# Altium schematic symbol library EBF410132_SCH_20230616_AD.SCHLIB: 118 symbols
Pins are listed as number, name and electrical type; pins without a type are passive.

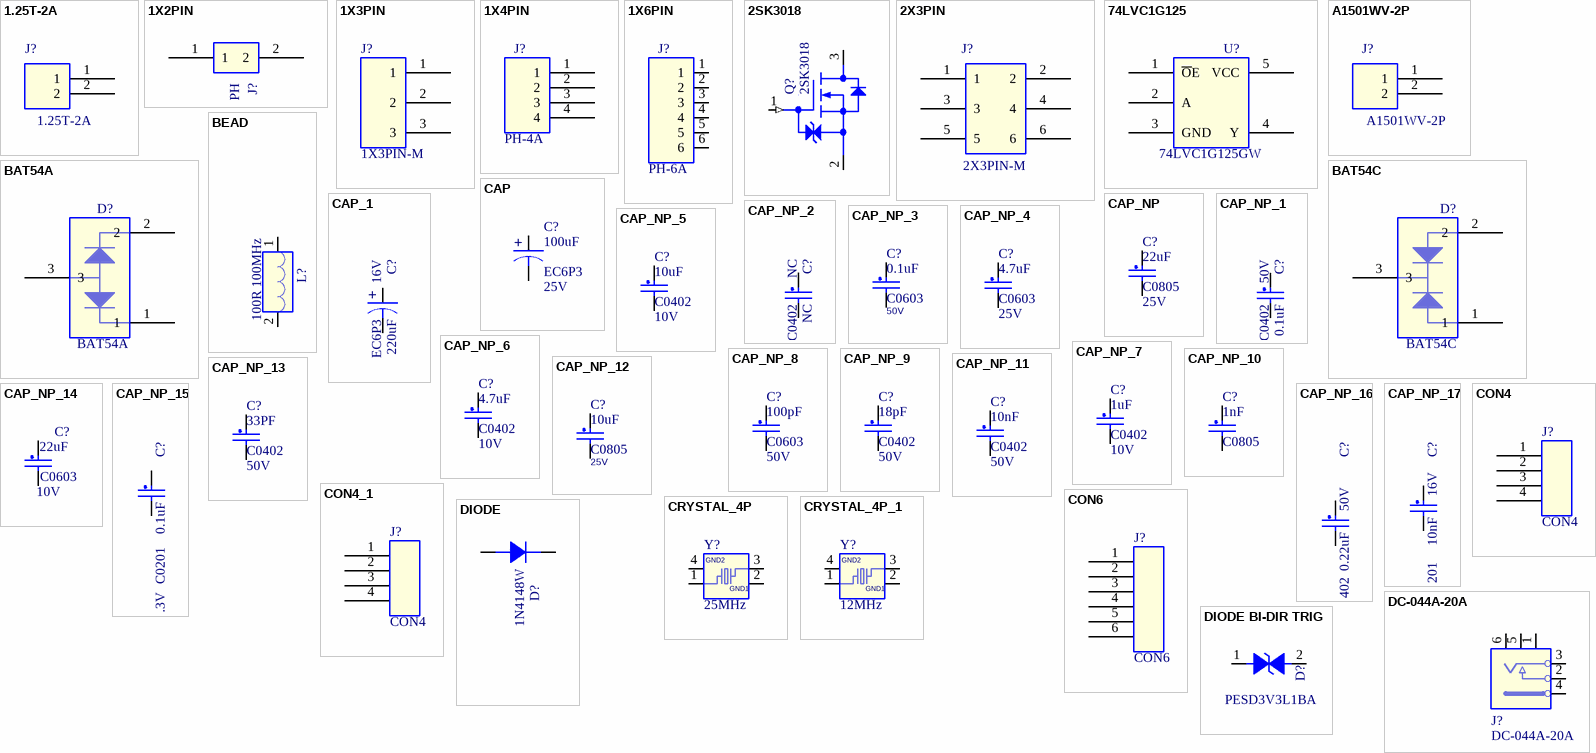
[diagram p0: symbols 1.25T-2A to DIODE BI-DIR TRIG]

## 1.25T-2A
designator J?
生命周期: 量产; 规格书: 1.25T-2A.pdf; 类别: 线对板连接器; 品牌: 创都; 条码: EBF29040105; 规格: GH1.25直插 2P针座连接器; PCB Footprint: gh1p25_th_2p
footprint gh1p25_th_2p
pins: 1, 2

## 1X2PIN
designator J?, comment PH
PCB Footprint: PH-1x2-2P0_l; 规格: 直针PH2.0-2P 间距2.0MM 拔插式 接插件; 规格编号: PH-2A; 条码: EBF29040005; 品牌: 博穆精密; 类别: PH连接器; 规格书: 博穆精密_PH2.0-A.pdf; 价格: 0.019031; 生命周期: 量产
footprint PH-1x2-2P0_l
pins: 1, 2

## 1X3PIN
designator J?, comment 1X3PIN-M
PCB Footprint: DIP_3p_2p54; 规格: 排针 总PIN数3 间距2.54mm 直插; 条码: EBF29020039; 类别: 直插单排排针; 生命周期: 量产; 规格书: 州日_单排针_直插_2P54.pdf
footprint DIP_3p_2p54
pins: 1, 2, 3

## 1X4PIN
designator J?, comment PH-4A
规格: 直针PH2.0-4P 间距2.0MM 拔插式 接插件; 条码: EBF29020025; 品牌: 博穆精密; 类别: PH连接器; 规格书: 博穆精密-PH2.0.pdf; 价格: 0.017; 生命周期: 量产; PCB Footprint: PH-1X4-2P0
footprint PH-1X4-2P0
pins: 1, 2, 3, 4

## 1X6PIN
designator J?, comment PH-6A
PCB Footprint: PH-1X6-2P0; 可替代料: EBF29020026; 生命周期: 量产; 价格: 0.0228; 规格书: 博穆精密_PH2.0-A.pdf; 类别: PH连接器; 品牌: 博穆精密; 规格: 直针PH2.0-6P 间距2.0MM 拔插式 接插件
footprint PH-1X6-2P0
pins: 1, 2, 3, 4, 5, 6

## 2SK3018
designator Q?
CLASS: IC; 丝印: KN; 生命周期: 量产; 价格: 0.120725; 规格书: 长电科技-2SK3018.pdf; 类别: N-MOS; 品牌: 江苏长电; 条码: EBF29280009; 规格: N沟道MOS 导通电阻8Ω 电流10mA 0.8V可驱动; PCB Footprint: SOT23
footprint SOT23
pins: 1 GATE (in), 2 SOURCE, 3 DRAIN

## 2X3PIN
designator J?, comment 2X3PIN-M
PCB Footprint: DIP-2X3-2P54; 生命周期: 量产; 类别: 直插双排排针; 条码: EBF29020030; 规格: 排针 总PIN数6 间距2.54mm 直插; 规格书: 州日_双排针_直插_2P54.pdf
footprint DIP-2X3-2P54
pins: 1, 2, 3, 4, 5, 6

## 74LVC1G125
designator U?, comment 74LVC1G125GW
规格: 时钟缓冲器 驱动器 具有三态输出 允许工作电压为3.3V 5.5V 典型工作电流100mA; 条码: EBF29170001; 品牌: 安世; 类别: 隔离器件; 规格书: 74LVC1G125GW.pdf; 价格: 0.182409; 生命周期: 量产; 丝印: VM; PCB Footprint: SOT-353
footprint SOT-353
pins: 1 ~{O}E, 2 A, 3 GND, 4 Y, 5 VCC

## A1501WV-2P
designator J?
PCB Footprint: zh1p5mm_th_2p; 品牌: 长江连接器; 规格: ZH1.5直插 镀锡 2P 针座连接器; 条码: EBF29040095; 类别: 线对板连接器; 规格书: A1501.pdf; 生命周期: 量产
footprint zh1p5mm_th_2p
pins: 1, 2

## BAT54A
designator D?
规格: 肖特基二极管 直流反向耐压30V 平均整流电流200mA 正向压降1V@100mA SOT-23; 条码: EBF29140065; 品牌: 晶导微电子; 类别: 贴片肖特基二极管; 规格书: 晶导微电子-BAT54S.pdf; 价格: 0.054466; 生命周期: 量产; PCB Footprint: SOT23
footprint SOT23
pins: 1, 2, 3

## BAT54C
designator D?
规格: 肖特基二极管 直流反向耐压30V 平均整流电流200mA 正向压降1V@100mA SOT-23; 条码: EBF29140014; 品牌: 萨科微; 类别: 贴片肖特基二极管; 规格书: BAT54C.pdf; 价格: 0.068489; 生命周期: 量产; 丝印: KL3; PCB Footprint: SOT23
footprint SOT23
pins: 1, 2, 3

## BEAD
designator L?, comment 100R 100MHz
CLASS: DISCRETE; 规格: 磁珠100Ω @100MHz 额定电流3A 直流电阻30mΩ; 规格编号: UPZ1608E101-3R0TF; 条码: EBF29050038; 品牌: 顺络; 类别: 贴片磁珠0603; 规格书: 顺络-磁珠.pdf; 价格: 0.021567; 生命周期: 量产; PCB Footprint: L0603
footprint L0603
pins: 1, 2

## CAP
designator C?, comment 100uF  PCB Footprint: EC6P3  Voltage: 25V
生命周期: 量产; 价格: 0.527539; 规格书: 台湾立隆-贴片型铝电解电容.pdf; 类别: 贴片型铝电解电容; 品牌: 台湾立隆; 条码: EBF29060142; 规格编号: VZL101M1ETR-0606; 规格: 贴片电解电容100uF 20% 25V 尺寸6.3mmX5.7mm 工作寿命：2000H@105℃
footprint T2012
footprint EC6P3
pins: 1, 2

## CAP_1
designator C?, comment 220uF  PCB Footprint: EC6P3  Voltage: 16V
规格: 贴片电解电容220uF 20% 16V 尺寸6.3mmX5.8mm 工作寿命：2000H@105℃; 规格编号: VZT221M1CTR-0606ACS; 条码: EBF29060148; 品牌: 台湾立隆; 类别: 贴片型铝电解电容; 规格书: 台湾立隆-贴片型铝电解电容.pdf; 价格: 0.566564; 生命周期: 量产
footprint T2012
footprint EC6P3
pins: 1, 2

## CAP_NP
designator C?, comment 22uF  PCB Footprint: C0805  Voltage: 25V
CLASS: DISCRETE; 规格: 贴片电容22uF 20% 25V X5R 0805; 规格编号: 0805X226M250NT; 条码: EBF29060173; 品牌: 风华; 类别: 贴片电容0805; 规格书: 风华电容.pdf; 价格: 0.285631; 生命周期: 量产
footprint C0805
pins: 1, 2

## CAP_NP_1
designator C?, comment 0.1uF  PCB Footprint: C0402  Voltage: 50V
CLASS: DISCRETE; 规格: 贴片电容0.1uF 10% 50V X5R 0402; 规格编号: 0402X104K500NT; 条码: EBF29060118; 品牌: 风华; 类别: 贴片电容0402; 规格书: 风华电容.pdf; 价格: 0.029826; 生命周期: 量产
footprint C0402
pins: 1, 2

## CAP_NP_2
designator C?, comment NC  PCB Footprint: C0402
CLASS: DISCRETE; 规格: 贴片电容NC 预留; 条码: EBF29060149; 类别: 贴片电容0402
footprint C0402
pins: 1, 2

## CAP_NP_3
designator C?, comment 0.1uF  PCB Footprint: C0603  Voltage: 50V
CLASS: DISCRETE; 规格: 贴片电容0.1uF 20% 50V Y5V 0603; 规格编号: 0603F104M500NT; 条码: EBF29060135; 品牌: 风华; 类别: 贴片电容0603; 规格书: 风华电容.pdf; 价格: 0.01438; 生命周期: 量产
footprint C0603
pins: 1, 2

## CAP_NP_4
designator C?, comment 4.7uF  PCB Footprint: C0603  Voltage: 25V
CLASS: DISCRETE; 规格: 贴片电容4.7uF 10% 25V X7R 0603; 规格编号: CL10A475KA8NQNC; 条码: EBF29060162; 品牌: 三星; 类别: 贴片电容0603; 规格书: 三星电容.pdf; 价格: 0.031274; 生命周期: 量产
footprint C0603
pins: 1, 2

## CAP_NP_5
designator C?, comment 10uF  PCB Footprint: C0402  Voltage: 10V
CLASS: DISCRETE; 规格: 贴片电容10uF 20% 10V X5R 0402; 规格编号: CL05A106MP8NUB8; 条码: EBF29060247; 品牌: 三星; 类别: 贴片电容0402; 规格书: 三星电容.pdf; 价格: 0.518415; 生命周期: 量产
footprint C0402
pins: 1, 2

## CAP_NP_6
designator C?, comment 4.7uF  PCB Footprint: C0402  Voltage: 10V
CLASS: DISCRETE; 规格: 贴片电容4.7uF 10% 10V X5R 0402; 规格编号: CC0402KRX5R6BB475; 条码: EBF29060248; 品牌: 国巨; 类别: 贴片电容0402; 规格书: 国巨-贴片电容.pdf; 价格: 0.059058; 生命周期: 量产
footprint C0402
pins: 1, 2

## CAP_NP_7
designator C?, comment 1uF  PCB Footprint: C0402  Voltage: 10V
CLASS: DISCRETE; 规格: 贴片电容1uF 10% 10V X5R 0402; 规格编号: 0402X105K100NT; 条码: EBF29060121; 品牌: 风华; 类别: 贴片电容0402; 规格书: 风华电容.pdf; 价格: 0.01191; 生命周期: 量产
footprint C0402
pins: 1, 2

## CAP_NP_8
designator C?, comment 100pF  PCB Footprint: C0603  Voltage: 50V
CLASS: DISCRETE; 生命周期: 量产; 价格: 0.014181; 规格书: 风华电容.pdf; 类别: 贴片电容0603; 品牌: 风华; 条码: EBF29060132; 规格编号: 0603CG101J500NT; 规格: 贴片电容100pF 5% 50V C0G 0603
footprint C0603
pins: 1, 2

## CAP_NP_9
designator C?, comment 18pF  PCB Footprint: C0402  Voltage: 50V
CLASS: DISCRETE; 生命周期: 量产; 价格: 0.00515; 规格书: 风华电容.pdf; 类别: 贴片电容0402; 品牌: 风华; 条码: EBF29060235; 规格编号: 0402CG180J500NT; 规格: 贴片电容18pF 5% 50V C0G 0402
footprint C0402
pins: 1, 2

## CAP_NP_10
designator C?, comment 1nF  PCB Footprint: C0805
CLASS: DISCRETE; 规格: 贴片电容1nF 10% 1kV X7R 0805; 规格编号: 0805B102K102CT; 条码: EBF29060304; 品牌: 华新科; 类别: 贴片电容0805; 规格书: 华新科0805系列高压贴片电容.pdf; 价格: 0.083527; 生命周期: 量产
footprint C0805
pins: 1, 2

## CAP_NP_11
designator C?, comment 10nF  PCB Footprint: C0402  Voltage: 50V
CLASS: DISCRETE; 规格: 贴片电容10nF 10% 50V X7R 0402; 规格编号: CC0402KRX7R9BB103; 条码: EBF29060245; 品牌: 国巨; 类别: 贴片电容0402; 规格书: 国巨-贴片电容.pdf; 价格: 0.003808; 生命周期: 量产
footprint C0402
pins: 1, 2

## CAP_NP_12
designator C?, comment 10uF  PCB Footprint: C0805  Voltage: 25V
CLASS: DISCRETE; 生命周期: 量产; 规格书: 三星贴片电容.pdf; 类别: 贴片电容0805; 品牌: 三星华; 条码: EBFCIS230423161132; 规格编号: CL21A106KAYNNNE; 规格: 贴片电容10uF 10% 25V X5R 0805
footprint C0805
pins: 1, 2

## CAP_NP_13
designator C?, comment 33PF  PCB Footprint: C0402  Voltage: 50V
CLASS: DISCRETE; 规格: 贴片电容33pF 5% 50V 0402; 规格编号: 0402CG330J500NT; 条码: EBF29060298; 品牌: 风华; 类别: 贴片电容0402; 规格书: 风华电容.pdf; 生命周期: 量产
footprint C0402
pins: 1, 2

## CAP_NP_14
designator C?, comment 22uF  PCB Footprint: C0603  Voltage: 10V
CLASS: DISCRETE; 生命周期: 量产; 价格: 0.078818; 规格书: 三星电容.pdf; 类别: 贴片电容0603; 品牌: 三星; 条码: EBF29060163; 规格编号: CL10A226MP8NUNE; 规格: 贴片电容22uF 20% 10V X5R 0603
footprint C0603
pins: 1, 2

## CAP_NP_15
designator C?, comment 0.1uF  PCB Footprint: C0201  Voltage: 6.3V
CLASS: DISCRETE; 规格: 贴片电容0.1uF 20% 6.3V X5R 0201; 规格编号: 0201X104M6R3NT; 条码: EBF29060223; 品牌: 风华; 类别: 贴片电容0201; 规格书: 风华电容.pdf; 生命周期: 量产
footprint C0201
pins: 1, 2

## CAP_NP_16
designator C?, comment 0.22uF  PCB Footprint: C0402  Voltage: 50V
CLASS: DISCRETE; 规格: 贴片电容0.22uF 20% 50V X5R 0402; 规格编号: UMK105BJ224MV-F; 条码: EBF29060266; 品牌: 太诱; 类别: 贴片电容0402; 规格书: 太诱-贴片电容.pdf; 价格: 0.074942; 生命周期: 量产
footprint C0402
pins: 1, 2

## CAP_NP_17
designator C?, comment 10nF  PCB Footprint: C0201  Voltage: 16V
CLASS: DISCRETE; 规格: 贴片电容10nF 20% 16V X5R 0201; 规格编号: 0201X103M160NT; 条码: EBF29060270; 品牌: 风华; 类别: 贴片电容0201; 规格书: 风华电容.pdf; 生命周期: 量产
footprint C0201
pins: 1, 2

## CON4
designator J?
生命周期: 量产; 价格: 0.198381; 规格书: 康奈克斯电气-绿色端子弯针插座.pdf; 类别: 绿色插拔式接线端子; 品牌: 康奈克斯电气; 条码: EBF29040009; 规格编号: WJ15EDGRC-3.81-4P; 规格: 插拔式接线端子 间距3.81mm 90度弯针 4PIN; PCB Footprint: DB2ERC-3P81-4P
footprint DB2ERC-3P81-4P
pins: 1, 2, 3, 4

## CON4_1
designator J?, comment CON4
PCB Footprint: XH2p54-4p; 规格: 直针XH2.54-4P 间距2.54MM 拔插式 接插件 直插; 规格编号: XH-4A; 条码: EBF29040012; 品牌: 博穆精密; 类别: XH连接器; 规格书: 博穆精密-XH2.54.pdf; 价格: 0.041116; 生命周期: 量产
footprint XH2p54-4p
pins: 1, 2, 3, 4

## CON6
designator J?
PCB Footprint: DB2ERC-3P81-6P; 规格: 绿色插拔式接线端子 间距3.81mm 90度弯针 6PIN; 规格编号: WJ15EDGRC-3.81-6P; 条码: EBF29040013; 品牌: 康奈克斯电气; 类别: 绿色插拔式接线端子; 规格书: 康奈克斯电气-绿色端子弯针插座.pdf; 价格: 0.301748; 生命周期: 量产
footprint DB2ERC-3P81-6P
pins: 1, 2, 3, 4, 5, 6

## CRYSTAL_4P
designator Y?, comment 25MHz
CLASS: IC; PCB Footprint: 3225; 生命周期: 量产; 价格: 0.385846; 规格书: 扬兴科技-25MHZ.pdf; 类别: 贴片晶振 3225; 品牌: 扬兴科技; 条码: EBF29100005; 规格编号: X322525MQB4SI; 规格: 无源晶振25MHZ 50Ω 16pF 3225
footprint 3225
pins: 1, 2 GND1 (power), 3, 4 GND2 (power)

## CRYSTAL_4P_1
designator Y?, comment 12MHz
CLASS: IC; PCB Footprint: 3225; 规格: 无源晶振12MHZ 80Ω 20pF 3225; 规格编号: X322512MSB4SI; 条码: EBF29100013; 品牌: 扬兴科技; 类别: 贴片晶振 3225; 规格书: 扬兴科技-贴片晶振.pdf; 价格: 0.327763; 生命周期: 量产
footprint 3225
pins: 1, 2 GND1 (power), 3, 4 GND2 (power)

## DC-044A-20A
designator J?
规格: DC-044A-20A DC插座; 规格编号: DC-044A-20A DC; 条码: EBF29040093; 类别: DC电源座; 规格书: DC插座_内径_2MM外径_5.9MM.pdf; 生命周期: 量产
footprint dc_in_th_3p_10r1x11r6
pins: 1, 2, 3, 4, 5, 6

## DIODE
designator D?, comment 1N4148W
PCB Footprint: SOD-123; 规格: 开关二极管 反向耐压值100V 平均整流电流150mA 正向压降1.25V 150mA 功率500mW; 条码: EBF29140015; 品牌: 江苏长电; 类别: 贴片开关二极管; 规格书: 1N4148WT4.pdf; 价格: 0.061637; 生命周期: 量产; 丝印: T4
footprint SOD-123
pins: 1 K, 2 A

## DIODE BI-DIR TRIG
designator D?, comment PESD3V3L1BA
PCB Footprint: sod323_t; 规格: 防静电保护ESD二极管 箝位电压26V 击穿电压5.8V 反向关断电压3.3V; 规格编号: PESD3V3L1BA 115; 条码: EBF29140003; 品牌: 安世; 类别: 贴片ESD; 规格书: 安世-PESD3V3L1BA-115.pdf; 价格: 0.31497; 生命周期: 量产; 丝印: AB
footprint D0603/SMD
footprint sod323_t
pins: 1, 2

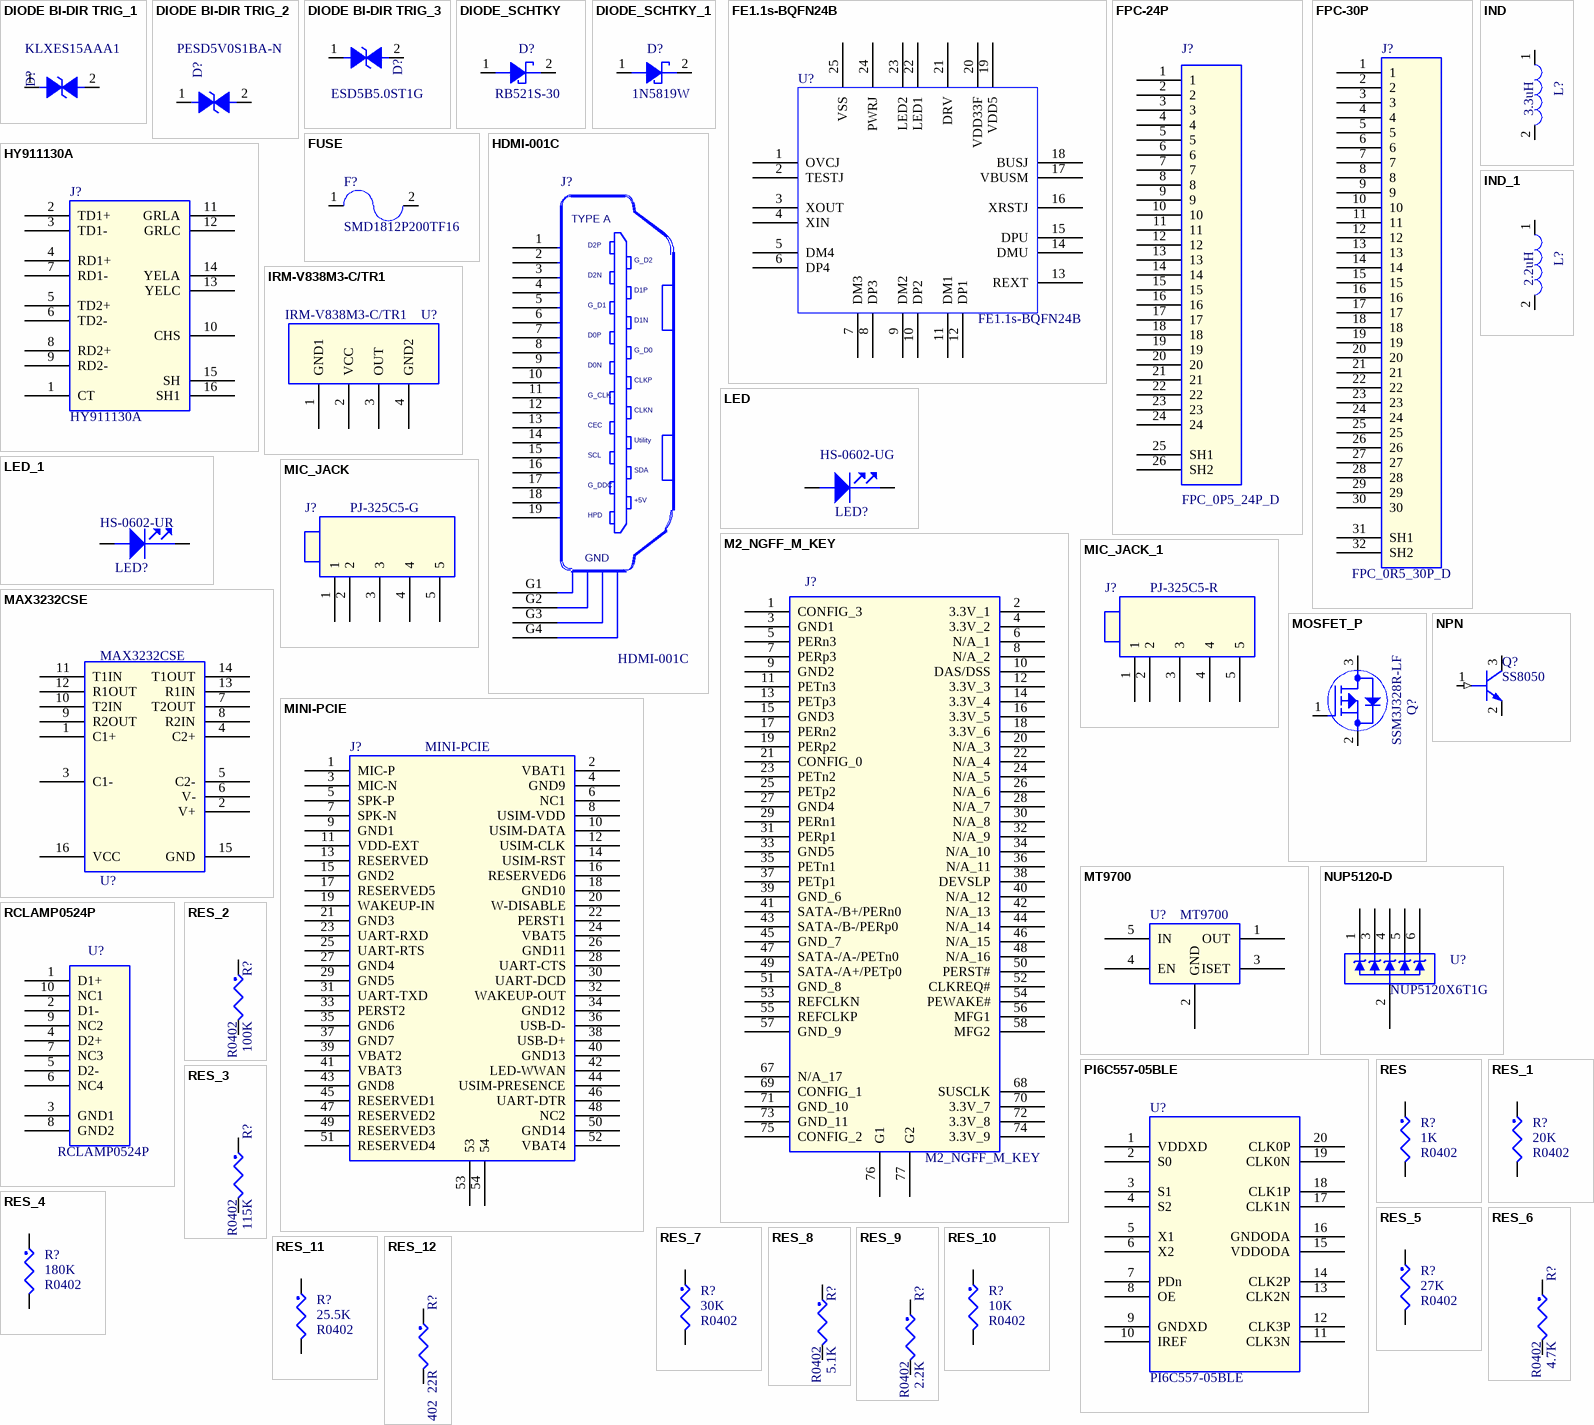
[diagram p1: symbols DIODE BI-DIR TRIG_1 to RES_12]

## DIODE BI-DIR TRIG_1
designator D?, comment KLXES15AAA1
PCB Footprint: ES0402; 生命周期: 量产; 价格: 0.09719; 规格书: KLXES15AAA1.pdf; 类别: 贴片ESD; 品牌: 永裕泰; 条码: EBF29140063; 规格: 用于 USB3.0、HDMI 0.5pF、5V、±15kV ESD 保护二极管
footprint D0603/SMD
footprint ES0402
pins: 1, 2

## DIODE BI-DIR TRIG_2
designator D?, comment PESD5V0S1BA-N
规格: 防静电保护ESD二极管 箝位电压21V 击穿电压6V 反向关断电压5V; 条码: EBF29140021; 品牌: 伯恩半导体; 类别: 贴片ESD; 规格书: 伯恩半导体-PESD5V0S1BA-N.pdf; 价格: 0.196644; 生命周期: 量产; PCB Footprint: SOD323
footprint D0603/SMD
footprint SOD323
pins: 1, 2

## DIODE BI-DIR TRIG_3
designator D?, comment ESD5B5.0ST1G
规格: 防静电保护ESD击穿电压5.8V 反向关断电压5V 极性 双向; 条码: EBF29140041; 品牌: 安森美; 类别: 贴片ESD; 规格书: 安森美_ESD5B5.0ST1G.pdf; 价格: 0.099336; 生命周期: 量产; PCB Footprint: sod523
footprint D0603/SMD
footprint sod523
pins: 1, 2

## DIODE_SCHTKY
designator D?, comment RB521S-30
CLASS: IC; 生命周期: 量产; 价格: 0.06781; 规格书: 江苏长电_RB521S-30.pdf; 类别: 贴片肖特基二极管; 品牌: 江苏长电; 条码: EBFCIS221114153437; 规格: 直流反向耐压(Vr)：30V 平均整流电流(Io)：200mA 正向压降(Vf)：500mV@200mA 30V@100mA,VF=350mV@10mA; PCB Footprint: SOD523
footprint SOD523
pins: 1, 2

## DIODE_SCHTKY_1
designator D?, comment 1N5819W
CLASS: IC; 丝印: SL; 生命周期: 量产; 价格: 0.175675; 规格书: 1N5819W.pdf; 类别: 贴片肖特基二极管; 品牌: 台湾迪嘉; 条码: EBF29140016; 规格: 肖特基二极管 直流反向耐压40V 平均整流电流1A 正向压降0.6V@1A SOD-123; PCB Footprint: SOD-123
footprint SOD-123
pins: 1, 2

## FE1.1s-BQFN24B
designator U?
PCB Footprint: QFN24; 生命周期: 量产; 规格书: FE1.1s-BQFN24B.pdf; 类别: USB芯片; 品牌: 汤铭科技; 条码: EBF29150035; 规格: USB HUB芯片 工作电压3.3V 5V 协议类别USB2.0 支持高速(480Mbps) 全速(12Mbps)和低速(1.5Mbps)模式
footprint QFN24
pins: 1 OVCJ, 2 TESTJ, 3 XOUT, 4 XIN, 5 DM4, 6 DP4, 7 DM3, 8 DP3, 9 DM2, 10 DP2, 11 DM1, 12 DP1, 13 REXT, 14 DMU, 15 DPU, 16 XRSTJ, 17 VBUSM, 18 BUSJ, 19 VDD5, 20 VDD33F, 21 DRV, 22 LED1, 23 LED2, 24 PWRJ, 25 VSS

## FPC-24P
designator J?, comment FPC_0P5_24P_D
可替代料: EBF29040059; 生命周期: 量产; 价格: 0.368739; 规格书: 钜硕电子-FPC间距0.5mm.pdf; 类别: FPC连接器; 品牌: 钜硕电子; 规格编号: AFC01-S24FCA-00; 规格: FPC连接器 针脚数24 间距0.5mmm 下接 卧贴 翻盖式; PCB Footprint: fpc_24p_0p5
footprint fpc_24p_0p5
pins: 1, 2, 3, 4, 5, 6, 7, 8, 9, 10, 11, 12, 13, 14, 15, 16, 17, 18, 19, 20, 21, 22, 23, 24, 25 SH1, 26 SH2

## FPC-30P
designator J?, comment FPC_0R5_30P_D
规格: FPC连接器 针脚数30 间距0.5mm 高度2.0mm 下接 卧贴 翻盖式; 规格编号: FPC-05F-30PH20; 条码: EBF29040079; 品牌: 讯普; 类别: FPC连接器; 规格书: FPC-05F-NPH20.pdf; 生命周期: 量产; PCB Footprint: FPC-30P-0P5
footprint FPC-30P-0P5
pins: 1, 2, 3, 4, 5, 6, 7, 8, 9, 10, 11, 12, 13, 14, 15, 16, 17, 18, 19, 20, 21, 22, 23, 24, 25, 26, 27, 28, 29, 30, 31 SH1, 32 SH2

## FUSE
designator F?, comment SMD1812P200TF16
生命周期: 量产; 价格: 0.385618; 规格书: 瑞隆源-自恢复保险丝.pdf; 类别: 自恢复保险丝; 品牌: 瑞隆源; 条码: EBF29270006; 规格: 自恢复保险丝 最大电压46V 最大电流100A 保持电流2A 跳闸电流4A; PCB Footprint: F1812
footprint F1812
pins: 1, 2

## HDMI-001C
designator J?
CLASS: IO; OriginalSymbolOrigin: (-200,650); Vendor: Comtek; VPN: 1166-2C105-211; PCB Footprint: HDMI-SMD; 生命周期: 量产; 规格书: HDMI-001C.pdf; 类别: HDMI连接器; 品牌: 讯普; 条码: EBF29040081; 规格: HDMI立式
footprint HDMI-SMD
pins: 1, 2, 3, 4, 5, 6, 7, 8, 9, 10, 11, 12, 13, 14, 15, 16, 17, 18, 19, G1 20, G2 21, G3 22, G4 23

## HY911130A
designator J?
规格: 屏蔽式以太网连接器RJ45 引脚数14 LED灯黄绿 1000M; 条码: EBF29040053; 品牌: 汉仁; 类别: 网口; 规格书: 汉仁_1000M_ HY911130A.pdf; 价格: 11.12; 生命周期: 量产
footprint HY911130A
pins: 1 CT, 2 TD1+, 3 TD1-, 4 RD1+, 5 TD2+, 6 TD2-, 7 RD1-, 8 RD2+, 9 RD2-, 10 CHS, 11 GRLA, 12 GRLC, 13 YELC, 14 YELA, 15 SH, 16 SH1

## IND
designator L?, comment 3.3uH
CLASS: DISCRETE; 生命周期: 量产; 规格书: 台庆-功率电感.pdf; 类别: 贴片电感0402; 品牌: 台庆; 条码: EBF29050040; 规格: 贴片电感3.3uH ±20% 3A 直流电阻69mΩ; 规格编号: TMPC0402HP-3R3MG-Z02; 价格: 1.5992; PCB Footprint: l4520
footprint l4520
pins: 1, 2

## IND_1
designator L?, comment 2.2uH
CLASS: DISCRETE; PCB Footprint: L2520; 生命周期: 量产; 价格: 0.129914; 规格书: 佳邦_ WIP252012P-2R2ML.pdf; 类别: 贴片电感2520; 品牌: 佳邦; 条码: EBFCIS220927171910; 规格编号: WIP252012P-2R2ML; 规格: 功率电感2.2uH 2.2uH ±20% 2.06A 85mΩ
footprint L2520
pins: 1, 2

## IRM-V838M3-C/TR1
designator U?
PCB Footprint: SMD4-6R80X2R50; 生命周期: 量产; 规格书: IRM-V838M3-C_TR1.pdf; 类别: 红外接收头; 品牌: 亿光; 条码: EBF29230005; 规格: 侧贴红外遥控接收头 工作电压2.7V~5.5V 兼容TTL与CMOS
footprint SMD4-6R80X2R50
pins: 1 GND1, 2 VCC, 3 OUT, 4 GND2

## LED
designator LED?, comment HS-0602-UG
PCB Footprint: led_hs_0602_ur; 规格: 正向电压(VF)：3.2V 工作电流：5mA 功率：80mW 绿色; 条码: EBF29140060; 品牌: 鸿之森; 类别: 侧贴发光LED; 规格书: HS-0602-UG.pdf; 价格: 0.068705; 生命周期: 量产
footprint led_hs_0602_ur
pins: 1 ANODE, 2 CATHODE

## LED_1
designator LED?, comment HS-0602-UR
PCB Footprint: led_hs_0602_ur; 生命周期: 量产; 规格书: HS-0602-UR.pdf; 类别: 侧贴发光LED; 品牌: 鸿之森; 条码: EBF29140054; 规格: 侧贴0602LED 红色
footprint led_hs_0602_ur
pins: 1 ANODE, 2 CATHODE

## M2_NGFF_M_KEY
designator J?
生命周期: 量产; 规格书: M.2NGFF-M-67PIN.pdf; 类别: 金手指连接器; 条码: EBF29040083; 规格: M.2NGFF高度5.5MMM.2连接器镀金30UMKEY67PIN
footprint M2_NGFF_M_KEY
pins: 1 CONFIG_3, 2 3.3V_1, 3 GND1, 4 3.3V_2, 5 PERn3, 6 N/A_1, 7 PERp3, 8 N/A_2, 9 GND2, 10 DAS/DSS, 11 PETn3, 12 3.3V_3, 13 PETp3, 14 3.3V_4, 15 GND3, 16 3.3V_5, 17 PERn2, 18 3.3V_6, 19 PERp2, 20 N/A_3, 21 CONFIG_0, 22 N/A_4, 23 PETn2, 24 N/A_5, 25 PETp2, 26 N/A_6, 27 GND4, 28 N/A_7, 29 PERn1, 30 N/A_8, 31 PERp1, 32 N/A_9, 33 GND5, 34 N/A_10, 35 PETn1, 36 N/A_11, 37 PETp1, 38 DEVSLP, 39 GND_6, 40 N/A_12, 41 SATA-/B+/PERn0, 42 N/A_13, 43 SATA-/B-/PERp0, 44 N/A_14, 45 GND_7, 46 N/A_15, 47 SATA-/A-/PETn0, 48 N/A_16, 49 SATA-/A+/PETp0, 50 PERST#, 51 GND_8, 52 CLKREQ#, 53 REFCLKN, 54 PEWAKE#, 55 REFCLKP, 56 MFG1, 57 GND_9, 58 MFG2, 67 N/A_17, 68 SUSCLK, 69 CONFIG_1, 70 3.3V_7, 71 GND_10, 72 3.3V_8, 73 GND_11, 74 3.3V_9, 75 CONFIG_2, 76 G1, 77 G2

## MAX3232CSE
designator U?
生命周期: 量产; 价格: 7.73; 规格书: MAX3232CSE.pdf; 类别: RS232芯片; 品牌: 美信; 条码: EBF29150006; 规格编号: MAX3232CSE+T; 规格: RS232芯片 收发器 驱动器/接收器数：2/2 协议类别RS232 电源电压3V~5.5V 数据速率235kbps; PCB Footprint: SOIC16
footprint 16
footprint SOIC16
pins: 1 C1+, 2 V+, 3 C1-, 4 C2+, 5 C2-, 6 V-, 7 T2OUT, 8 R2IN, 9 R2OUT, 10 T2IN, 11 T1IN, 12 R1OUT, 13 R1IN, 14 T1OUT, 15 GND (power), 16 VCC (power)

## MIC_JACK
designator J?, comment PJ-325C5-G
PCB Footprint: EAR_JACK; 规格: 音频插座 耳机插座 双声道 3.5mm耳机座 5脚 绿; 条码: EBF29020024; 品牌: 中国星坤; 类别: 耳机座; 规格书: 星坤-音频连接器.pdf; 价格: 0.24; 生命周期: 量产
footprint EAR_JACK
pins: 1, 2, 3, 4, 5

## MIC_JACK_1
designator J?, comment PJ-325C5-R
PCB Footprint: EAR_JACK; 规格: 音频插座 耳机插座 双声道 3.5mm耳机座 5脚 粉; 条码: EBF29020023; 品牌: 中国星坤; 类别: 耳机座; 规格书: 星坤-音频连接器.pdf; 价格: 0.24; 生命周期: 量产
footprint EAR_JACK
pins: 1, 2, 3, 4, 5

## MINI-PCIE
designator J?
PCB Footprint: pcie_52p; 可替代料: EBF29040055; 生命周期: 量产; 价格: 1.935; 规格书: XUNPU(讯普)_52PMINIPCIE插座.pdf; 类别: 金手指连接器; 品牌: 讯普; 规格编号: PCIE-52P56H; 规格: MINI PCIE插座 引脚数：52P
footprint pcie_52p
pins: 1 MIC-P, 2 VBAT1, 3 MIC-N, 4 GND9, 5 SPK-P, 6 NC1, 7 SPK-N, 8 USIM-VDD, 9 GND1, 10 USIM-DATA, 11 VDD-EXT, 12 USIM-CLK, 13 RESERVED, 14 USIM-RST, 15 GND2, 16 RESERVED6, 17 RESERVED5, 18 GND10, 19 WAKEUP-IN, 20 W-DISABLE, 21 GND3, 22 PERST1, 23 UART-RXD, 24 VBAT5, 25 UART-RTS, 26 GND11, 27 GND4, 28 UART-CTS, 29 GND5, 30 UART-DCD, 31 UART-TXD, 32 WAKEUP-OUT, 33 PERST2, 34 GND12, 35 GND6, 36 USB-D-, 37 GND7, 38 USB-D+, 39 VBAT2, 40 GND13, 41 VBAT3, 42 LED-WWAN, 43 GND8, 44 USIM-PRESENCE, 45 RESERVED1, 46 UART-DTR, 47 RESERVED2, 48 NC2, 49 RESERVED3, 50 GND14, 51 RESERVED4, 52 VBAT4, 53, 54

## MOSFET_P
designator Q?, comment SSM3J328R-LF
CLASS: IC; PCB Footprint: SOT23; 规格: P沟道MOS 导通电阻29.8mΩ 电流3A 1.5V可驱动; 规格编号: SSM3J328R LF; 条码: EBF29280008; 品牌: 东芝; 类别: P-MOS; 规格书: SSM3J328R-LF.pdf; 价格: 0.447836; 生命周期: 量产; 丝印: KFH-XXX
footprint SOT23
pins: 1 GATE, 2 SOURCE, 3 DRAIN

## MT9700
designator U?
丝印: D00HA-X; 生命周期: 量产; 价格: 0.483492; 规格书: MT9700.pdf; 类别: 功率开关; 品牌: 西安航天民芯; 条码: EBF29280004; 规格: 负载开关 工作电压2.4V-5.5V 最大电流2A 过流保护; PCB Footprint: SOT23-5
footprint SOT23-5
pins: 1 OUT, 2 GND, 3 ISET, 4 EN, 5 IN

## NPN
designator Q?, comment SS8050
CLASS: IC; PCB Footprint: SOT23; 规格: 贴片三极管SS8050 集电极电流1.5A 额定功率300mW NPN; 条码: EBF29090001; 品牌: 江苏长电; 类别: 贴片三极管SOT-23; 规格书: 江苏长电-SS8050Y1.pdf; 价格: 0.086744; 生命周期: 量产; 丝印: Y1
footprint SOT23
pins: 1 BASE (in), 2 EMITTER, 3 COLLECTOR

## NUP5120-D
designator U?, comment NUP5120X6T1G
PCB Footprint: SOT563; 生命周期: 量产; 价格: 0.39; 规格书: 安森美_NUP5120X6T1G.pdf; 类别: 贴片ESD; 品牌: 安森美; 条码: EBF29140034; 规格: 防静电保护ESD二极管 击穿电压6.2V 反向关断电压5V 封装SOT-523
footprint SOT563
pins: 1, 2, 3, 4, 5, 6

## PI6C557-05BLE
designator U?
PCB Footprint: tssop20; 生命周期: 量产; 价格: 19.49; 规格书: PI6C557-05BLE.pdf; 类别: 时钟信号发生器; 品牌: 美台; 条码: EBF29180005; 规格: PCIe Gen 3 时钟发生器 工作电压2.97V~3.63 输入频率：25MHz 最大输出频率：200MHz
footprint TSSOP20
pins: 1 VDDXD, 2 S0, 3 S1, 4 S2, 5 X1, 6 X2, 7 PDn, 8 OE, 9 GNDXD, 10 IREF, 11 CLK3N, 12 CLK3P, 13 CLK2N, 14 CLK2P, 15 VDDODA, 16 GNDODA, 17 CLK1N, 18 CLK1P, 19 CLK0N, 20 CLK0P

## RCLAMP0524P
designator U?
规格: TVS二极管 箝位电压17V 击穿电压8V 反向关断电压5V; 条码: EBF29140046; 品牌: 台舟; 类别: 贴片TVS; 规格书: 台舟-RCLAMP0524P.pdf; 价格: 0.185957; 生命周期: 量产; PCB Footprint: USON_10
footprint USON_10
pins: 1 D1+, 2 D1-, 3 GND1, 4 D2+, 5 D2-, 6 NC4, 7 NC3, 8 GND2, 9 NC2, 10 NC1

## RES
designator R?, comment 1K  PCB Footprint: R0402
CLASS: DISCRETE; 规格: 贴片电阻1K 1% 1/16W 0402; 规格编号: RI0402L1001FT; 条码: EBF29070050; 品牌: 合科泰; 类别: 贴片电阻0402; 规格书: 合科泰-RI系列电阻.pdf; 生命周期: 量产
footprint R0402
pins: 1, 2

## RES_1
designator R?, comment 20K  PCB Footprint: R0402
CLASS: DISCRETE; 规格: 贴片电阻20K 1% 1/16W 0402; 规格编号: 0402WGF2002TCE; 条码: EBF29070223; 品牌: 厚声; 类别: 贴片电阻0402; 规格书: 厚声-无铅厚膜电阻.pdf; 价格: 0.002473; 生命周期: 量产
footprint R0402
pins: 1, 2

## RES_2
designator R?, comment 100K  PCB Footprint: R0402
CLASS: DISCRETE; 规格: 贴片电阻100K 1% 1/16W 0402; 规格编号: RI0402L1003FT; 条码: EBF29070054; 品牌: 合科泰; 类别: 贴片电阻0402; 规格书: 合科泰-RI系列电阻.pdf; 生命周期: 量产
footprint R0402
pins: 1, 2

## RES_3
designator R?, comment 115K  PCB Footprint: R0402
CLASS: DISCRETE; 生命周期: 量产; 价格: 0.006087; 规格书: YAGEO国巨厚膜无铅电阻.pdf; 类别: 贴片电阻0402; 品牌: 国巨; 条码: EBF29070290; 规格编号: AC0402FR-07115KL; 规格: 贴片电阻115K 1% 1/16W 0402
footprint R0402
pins: 1, 2

## RES_4
designator R?, comment 180K  PCB Footprint: R0402
CLASS: DISCRETE; 规格: 贴片电阻180K 1% 1/16W 0402; 规格编号: CQ02WGF1803TCE; 条码: EBF29070288; 品牌: 厚声; 类别: 贴片电阻0402; 规格书: 厚声-无铅厚膜电阻.pdf; 价格: 0.006152; 生命周期: 量产
footprint R0402
pins: 1, 2

## RES_5
designator R?, comment 27K  PCB Footprint: R0402
CLASS: DISCRETE; 规格: 贴片电阻27K 1% 1/16W 0402; 规格编号: AC0402FR-0727KL; 条码: EBF29070003; 品牌: 国巨; 类别: 贴片电阻0402; 规格书: YAGEO国巨厚膜无铅电阻.pdf; 价格: 0.007054; 生命周期: 量产
footprint R0402
pins: 1, 2

## RES_6
designator R?, comment 4.7K  PCB Footprint: R0402
CLASS: DISCRETE; 生命周期: 量产; 规格书: 合科泰-RI系列电阻.pdf; 类别: 贴片电阻0402; 品牌: 合科泰; 条码: EBF29070047; 规格编号: RI0402L4701FT; 规格: 贴片电阻4.7K 1% 1/16W 0402
footprint R0402
pins: 1, 2

## RES_7
designator R?, comment 30K  PCB Footprint: R0402
CLASS: DISCRETE; 规格: 贴片电阻30K 1% 1/16W 0402; 规格编号: RI0402L3002FT; 条码: EBF29070048; 品牌: 合科泰; 类别: 贴片电阻0402; 规格书: 合科泰-RI系列电阻.pdf; 生命周期: 量产
footprint R0402
pins: 1, 2

## RES_8
designator R?, comment 5.1K  PCB Footprint: R0402
CLASS: DISCRETE; 生命周期: 量产; 类别: 贴片电阻0402; 品牌: VO; 条码: EBF29070258; 规格编号: 0402F5101BV1906130014; 规格: 贴片电阻5.1K 1% 1/16W 0402
footprint R0402
pins: 1, 2

## RES_9
designator R?, comment 2.2K  PCB Footprint: R0402
CLASS: DISCRETE; 生命周期: 量产; 规格书: 合科泰-RI系列电阻.pdf; 类别: 贴片电阻0402; 品牌: 合科泰; 条码: EBF29070051; 规格编号: RI0402L2201FT; 规格: 贴片电阻2.2K 1% 1/16W 0402
footprint R0402
pins: 1, 2

## RES_10
designator R?, comment 10K  PCB Footprint: R0402
CLASS: DISCRETE; 规格: 贴片电阻10K 1% 1/16W 0402; 规格编号: 0402WGF1002TCE; 条码: EBF29070046; 品牌: 厚声; 类别: 贴片电阻0402; 规格书: 厚声-无铅厚膜电阻.pdf; 价格: 0.002773; 生命周期: 量产
footprint R0402
pins: 1, 2

## RES_11
designator R?, comment 25.5K  PCB Footprint: R0402
CLASS: DISCRETE; 生命周期: 量产; 价格: 0.006152; 规格书: 厚声-无铅厚膜电阻.pdf; 类别: 贴片电阻0402; 品牌: 厚声; 条码: EBF29070291; 规格编号: CQ02WGF2552TCE; 规格: 贴片电阻25.5K 1% 1/16W 0402
footprint R0402
pins: 1, 2

## RES_12
designator R?, comment 22R  PCB Footprint: R0402
CLASS: DISCRETE; 规格: 贴片电阻22R 1% 1/16W 0402; 规格编号: RI0402L22R0FT; 条码: EBF29070181; 品牌: 合科泰; 类别: 贴片电阻0402; 规格书: 合科泰-RI系列电阻.pdf; 生命周期: 量产
footprint R0402
pins: 1, 2

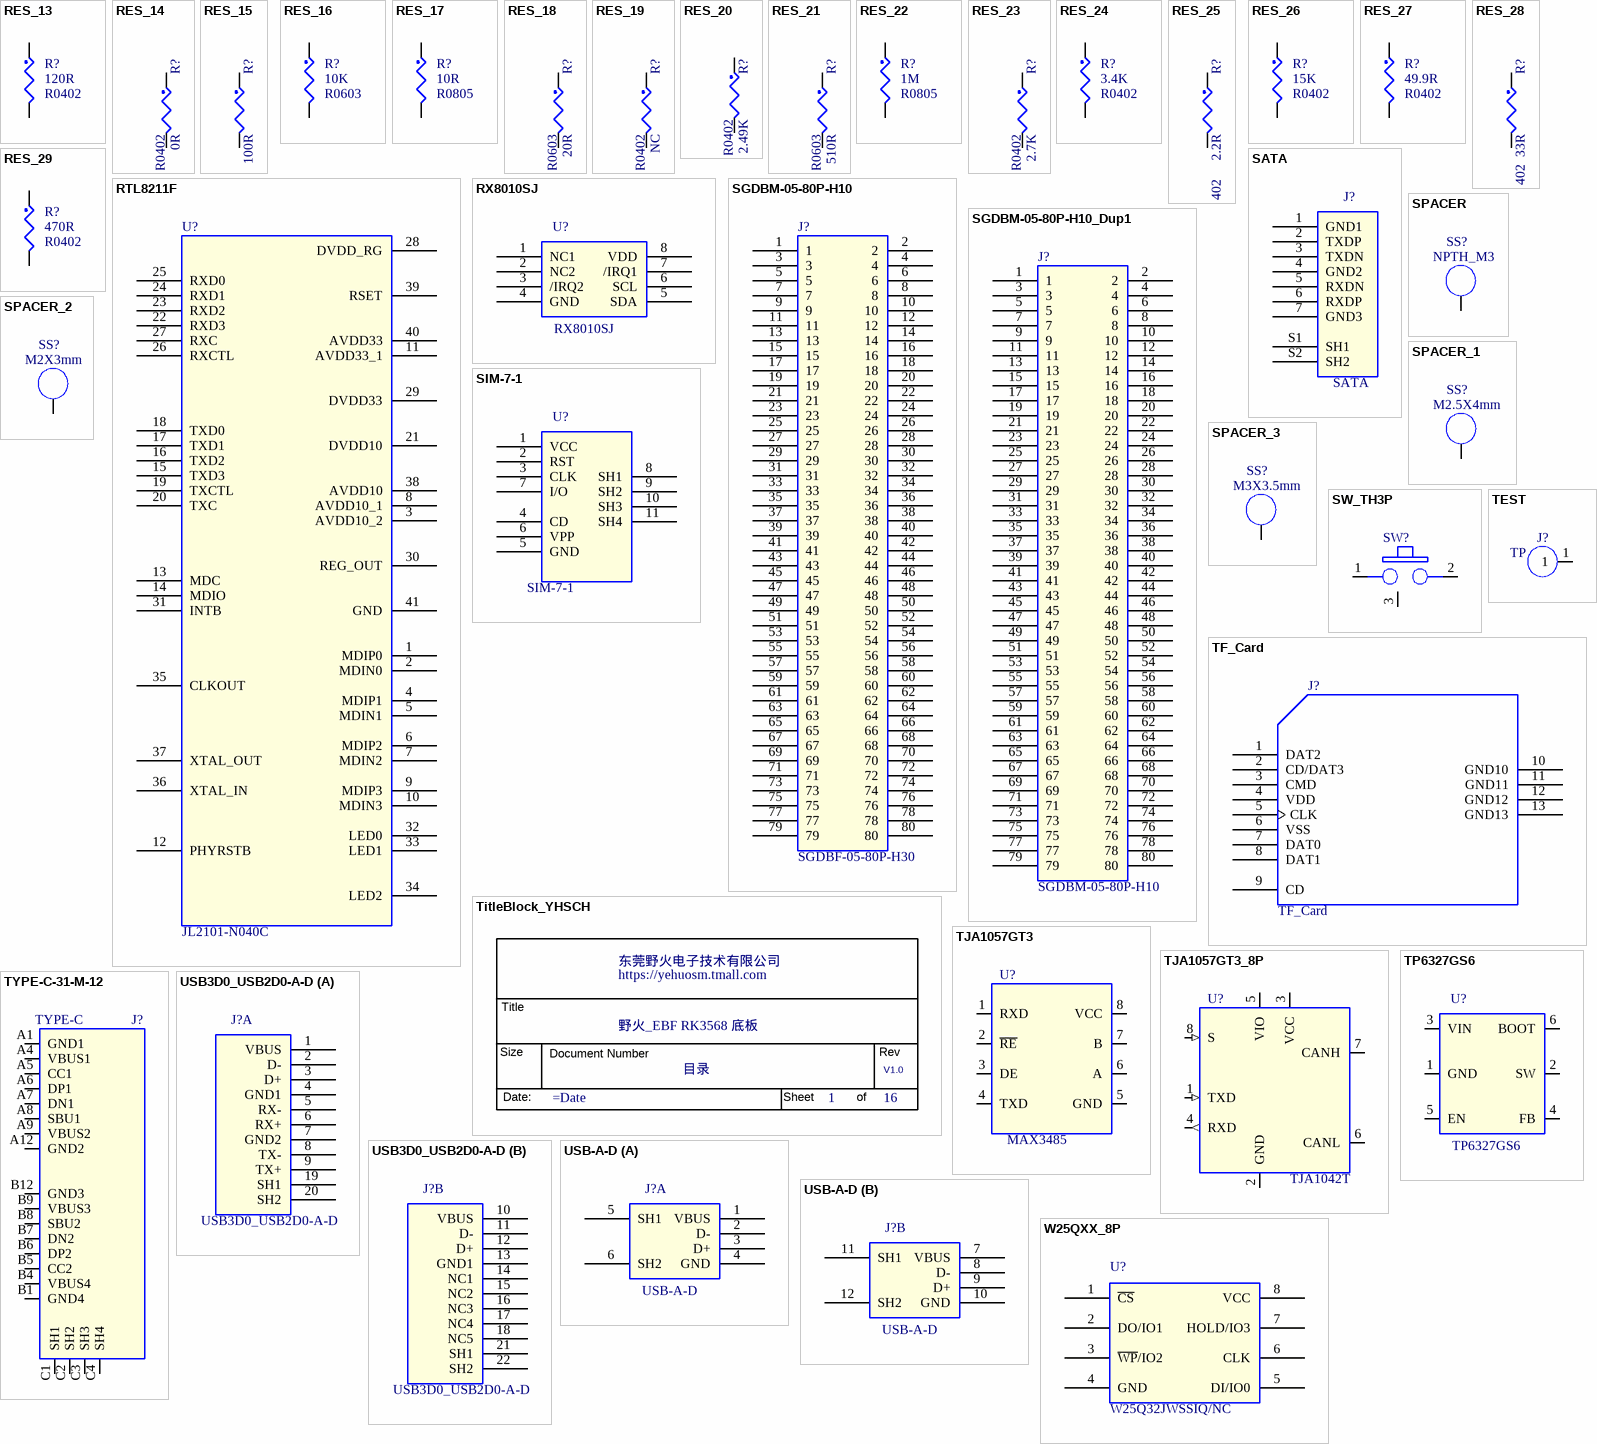
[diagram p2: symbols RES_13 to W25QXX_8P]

## RES_13
designator R?, comment 120R  PCB Footprint: R0402
CLASS: DISCRETE; 生命周期: 量产; 规格书: 厚声-无铅厚膜电阻.pdf; 类别: 贴片电阻0402; 品牌: 厚声; 条码: EBF29070275; 规格编号: 0402WGF1200TCE; 规格: 贴片电阻120R 1% 1/16W 0402; 价格: 0.002198
footprint R0402
pins: 1, 2

## RES_14
designator R?, comment 0R  PCB Footprint: R0402
CLASS: DISCRETE; 规格: 贴片电阻0R 1% 1/16W 0402; 规格编号: RI0402L000FT; 条码: EBF29070049; 品牌: 合科泰; 类别: 贴片电阻0402; 规格书: 合科泰-RI系列电阻.pdf; 生命周期: 量产
footprint R0402
pins: 1, 2

## RES_15
designator R?, comment 100R
CLASS: DISCRETE; PCB Footprint: R0402; 生命周期: 量产; 规格书: 合科泰-RI系列电阻.pdf; 类别: 贴片电阻0402; 品牌: 合科泰; 条码: EBF29070053; 规格编号: RI0402L1000FT; 规格: 贴片电阻100R 1% 1/16W 0402
footprint R0402
pins: 1, 2

## RES_16
designator R?, comment 10K  PCB Footprint: R0603
CLASS: DISCRETE; 规格: 贴片电阻10K 1% 1/10W 0603; 规格编号: RI0603L1002FT; 条码: EBF29070074; 品牌: 合科泰; 类别: 贴片电阻0603; 规格书: 合科泰-RI系列电阻.pdf; 生命周期: 量产
footprint R0603
pins: 1, 2

## RES_17
designator R?, comment 10R  PCB Footprint: R0805
CLASS: DISCRETE; 规格: 贴片电阻10R 1% 1/8W 0805; 规格编号: 0805W8F100JT5E; 条码: EBF29070197; 品牌: 厚声; 类别: 贴片电阻0805; 规格书: 厚声-无铅厚膜电阻.pdf; 价格: 0.0093; 生命周期: 量产
footprint R0805
pins: 1, 2

## RES_18
designator R?, comment 20R  PCB Footprint: R0603
CLASS: DISCRETE; 生命周期: 量产; 规格书: 合科泰-RI系列电阻.pdf; 类别: 贴片电阻0603; 品牌: 合科泰; 条码: EBF29070065; 规格编号: RI0603L20R0FT; 规格: 贴片电阻20R 1% 1/10W 0603
footprint R0603
pins: 1, 2

## RES_19
designator R?, comment NC  PCB Footprint: R0402
CLASS: DISCRETE; 规格: 贴片电阻NC 预留; 条码: EBF29070087; 类别: 贴片电阻0402
footprint R0402
pins: 1, 2

## RES_20
designator R?, comment 2.49K  PCB Footprint: R0402
CLASS: DISCRETE; 价格: 0.004709; 生命周期: 量产; 规格书: 厚声-无铅厚膜电阻.pdf; 类别: 贴片电阻0402; 品牌: 厚声; 条码: EBF29070292; 规格编号: 0402WGF2491TCE; 规格: 贴片电阻2.49K 1% 1/16W 0402
footprint R0402
pins: 1, 2

## RES_21
designator R?, comment 510R  PCB Footprint: R0603
CLASS: DISCRETE; 生命周期: 量产; 规格书: 合科泰-RI系列电阻.pdf; 类别: 贴片电阻0603; 品牌: 合科泰; 条码: EBF29070091; 规格编号: RI0603L5100FT; 规格: 贴片电阻510R 1% 1/10W 0603
footprint R0603
pins: 1, 2

## RES_22
designator R?, comment 1M  PCB Footprint: R0805
CLASS: DISCRETE; 生命周期: 量产; 价格: 0.02396; 规格书: YAGEO国巨厚膜无铅电阻.pdf; 类别: 贴片电阻0805; 品牌: 国巨; 条码: EBF29070294; 规格编号: AC0805FR-071ML; 规格: 贴片电阻1M 1% 1/8W 0805
footprint R0805
pins: 1, 2

## RES_23
designator R?, comment 2.7K  PCB Footprint: R0402
CLASS: DISCRETE; 规格: 贴片电阻2.7K 1% 1/16W 0402; 规格编号: RMC04022.7K1%N; 条码: EBF29070202; 品牌: 幸亚; 类别: 贴片电阻0402; 规格书: 幸亚电阻.pdf; 价格: 0.016497; 生命周期: 量产
footprint R0402
pins: 1, 2

## RES_24
designator R?, comment 3.4K  PCB Footprint: R0402
CLASS: DISCRETE; 生命周期: 量产; 规格书: 合科泰-RI系列电阻.pdf; 类别: 贴片电阻0402; 品牌: 合科泰; 条码: EBF29070186; 规格编号: RI0402L3401FT; 规格: 贴片电阻3.4K 1% 1/16W 0402
footprint R0402
pins: 1, 2

## RES_25
designator R?, comment 2.2R  PCB Footprint: R0402
CLASS: DISCRETE; 规格: 贴片电阻2.2R 1% 1/16W 0402; 规格编号: 0402WGF220KTCE; 条码: EBF29070280; 品牌: 厚声; 类别: 贴片电阻0402; 规格书: 厚声-无铅厚膜电阻.pdf; 价格: 0.003072; 生命周期: 量产
footprint R0402
pins: 1, 2

## RES_26
designator R?, comment 15K  PCB Footprint: R0402
CLASS: DISCRETE; 生命周期: 量产; 规格书: 合科泰-RI系列电阻.pdf; 类别: 贴片电阻0402; 品牌: 合科泰; 条码: EBF29070222; 规格编号: RI0402L1502FT; 规格: 贴片电阻15K 1% 1/16W 0402
footprint R0402
pins: 1, 2

## RES_27
designator R?, comment 49.9R  PCB Footprint: R0402
CLASS: DISCRETE; 规格: 贴片电阻49.9R 1% 1/16W 0402; 规格编号: 0402WGF499JTCE; 条码: EBF29070059; 品牌: 厚声; 类别: 贴片电阻0402; 规格书: 厚声-无铅厚膜电阻.pdf; 价格: 0.002703; 生命周期: 量产
footprint R0402
pins: 1, 2

## RES_28
designator R?, comment 33R  PCB Footprint: R0402
CLASS: DISCRETE; 规格: 贴片电阻33R 1% 1/16W 0402; 规格编号: 0402WGF330JTCE; 条码: EBF29070187; 品牌: 厚声; 类别: 贴片电阻0402; 规格书: 厚声-无铅厚膜电阻.pdf; 价格: 0.002158; 生命周期: 量产
footprint R0402
pins: 1, 2

## RES_29
designator R?, comment 470R  PCB Footprint: R0402
CLASS: DISCRETE; 规格: 贴片电阻470R 1% 1/16W 0402; 规格编号: 0402WGF4700TCE; 条码: EBF29070284; 品牌: 厚声; 类别: 贴片电阻0402; 规格书: 厚声-无铅厚膜电阻.pdf; 价格: 0.002728; 生命周期: 量产
footprint R0402
pins: 1, 2

## RTL8211F
designator U?, comment JL2101-N040C
PCB Footprint: qfp_40p_r; 规格: 以太网芯片 10M/100M/1000M 控制接口：RGMII RGMII电压：3.3V/2.5V/1.8V/1.5V; 条码: EBF29150043; 品牌: 景略半导体; 类别: 以太网芯片; 规格书: 景略半导体-JL2101-v1.07.pdf; 生命周期: 量产
footprint qfp_40p_r
pins: 1 MDIP0, 2 MDIN0, 3 AVDD10_2, 4 MDIP1, 5 MDIN1, 6 MDIP2, 7 MDIN2, 8 AVDD10_1, 9 MDIP3, 10 MDIN3, 11 AVDD33_1, 12 PHYRSTB, 13 MDC, 14 MDIO, 15 TXD3, 16 TXD2, 17 TXD1, 18 TXD0, 19 TXCTL, 20 TXC, 21 DVDD10, 22 RXD3, 23 RXD2, 24 RXD1, 25 RXD0, 26 RXCTL, 27 RXC, 28 DVDD_RG, 29 DVDD33, 30 REG_OUT, 31 INTB, 32 LED0, 33 LED1, 34 LED2, 35 CLKOUT, 36 XTAL_IN, 37 XTAL_OUT, 38 AVDD10, 39 RSET, 40 AVDD33, 41 GND

## RX8010SJ
designator U?
规格: 工作电压1.6V~5.5V 日期格式YY-MM-DD 时间格式HH:MM:SS 接口类型I2C 存储器容量16B 电流消耗350nA @ 5V; 条码: EBF29180001; 品牌: 爱普生; 类别: 实时时钟芯片; 规格书: 爱普生-RX8010SJ.pdf; 价格: 34.17; 生命周期: 量产; PCB Footprint: SOP-8
footprint SOP-8
pins: 1 NC1, 2 NC2, 3 /IRQ2, 4 GND, 5 SDA, 6 SCL, 7 /IRQ1, 8 VDD

## SATA
designator J?
PCB Footprint: ssata_v; 生命周期: 量产; 规格书: SATA_7PIN.pdf; 类别: SATA连接器; 品牌: 华宇创; 条码: EBF29040076; 规格编号: HYCW01-SATA07-205B; 规格: SATA 7PIN 全包开窗 A型
footprint ssata_v
pins: 1 GND1, 2 TXDP, 3 TXDN, 4 GND2, 5 RXDN, 6 RXDP, 7 GND3, S1 SH1 (power), S2 SH2 (power)

## SGDBM-05-80P-H10
designator J?, comment SGDBF-05-80P-H30
规格: 0.5mm BTB母座2*40P 双槽 立贴式 合高4.0mm; 条码: EBFCIS221220165510; 品牌: 山谷道; 类别: BTB连接器; 规格书: 山谷道_双槽板对板公母立贴式0_5mm.pdf; 生命周期: 量产
footprint SGDBF-05-80P-H30
pins: 1, 2, 3, 4, 5, 6, 7, 8, 9, 10, 11, 12, 13, 14, 15, 16, 17, 18, 19, 20, 21, 22, 23, 24, 25, 26, 27, 28, 29, 30, 31, 32, 33, 34, 35, 36, 37, 38, 39, 40, 41, 42, 43, 44, 45, 46, 47, 48, 49, 50, 51, 52, 53, 54, 55, 56, 57, 58, 59, 60, 61, 62, 63, 64, 65, 66, 67, 68, 69, 70, 71, 72, 73, 74, 75, 76, 77, 78, 79, 80

## SGDBM-05-80P-H10_Dup1
designator J?, comment SGDBM-05-80P-H10
生命周期: 量产; 规格书: 山谷道_双槽板对板公母立贴式0_5mm.pdf; 类别: BTB连接器; 品牌: 山谷道; 条码: EBFCIS221220164941; 规格: 0.5mm BTB公座2*40P 双槽 立贴式 合高4.0mm
footprint SGDBM-05-80P-H10
pins: 1, 2, 3, 4, 5, 6, 7, 8, 9, 10, 11, 12, 13, 14, 15, 16, 17, 18, 19, 20, 21, 22, 23, 24, 25, 26, 27, 28, 29, 30, 31, 32, 33, 34, 35, 36, 37, 38, 39, 40, 41, 42, 43, 44, 45, 46, 47, 48, 49, 50, 51, 52, 53, 54, 55, 56, 57, 58, 59, 60, 61, 62, 63, 64, 65, 66, 67, 68, 69, 70, 71, 72, 73, 74, 75, 76, 77, 78, 79, 80

## SIM-7-1
designator U?
PCB Footprint: nano_sim; 可替代料: EBF29040054; 生命周期: 量产; 价格: 1.48; 规格书: 华宇创_NANOSIMPUSH1.37H带CDPIN带柱.pdf; 类别: SIM卡座连接器; 品牌: 华宇创; 规格编号: HYC63-SIM07-137; 规格: nano sim卡座
footprint nano_sim
pins: 1 VCC, 2 RST, 3 CLK, 4 CD, 5 GND, 6 VPP, 7 I/O, 8 SH1, 9 SH2, 10 SH3, 11 SH4

## SPACER
designator SS?, comment NPTH_M3
CLASS: IC; 规格编号: M3螺丝孔_无铜; 条码: EBFCIS220926102704; 品牌: 野火科技有限公司; 类别: M3螺丝孔; 生命周期: 量产
footprint NPTH_M3
pins: 1 NC_1

## SPACER_1
designator SS?, comment M2.5X4mm
CLASS: IC; PCB Footprint: SMTSO-M2r5; 规格: SMT贴片螺母M2.5 台阶高度1.4MM 台阶外径：4.5MM 螺柱长度：4MM; 规格编号: SMTSO2540CTJ; 条码: EBFCIS230525101139; 品牌: 雄和远景; 类别: 贴片螺母; 规格书: 雄和远景_SMTSO2530CTJ.pdf; 生命周期: 量产; 备注: BTB核心板固定铜柱
footprint SMTSO-M2r5
pins: 1 NC_1

## SPACER_2
designator SS?, comment M2X3mm
CLASS: IC; 规格: SMT贴片螺母M2 高度3MM 台阶外径：4.5MM 整体高度：4.5MM 焊接孔外径：3MM; 规格编号: ZIY01-001; 条码: EBF500026; 品牌: 雄和远景; 类别: 贴片螺母; 规格书: 雄和远景_SMTWE2040CTJ.pdf; 生命周期: 量产; PCB Footprint: t3r2-5r2_topsmt
footprint t3r2-5r2_topsmt
pins: 1 NC_1

## SPACER_3
designator SS?, comment M3X3.5mm
CLASS: IC; PCB Footprint: smtso-m3; 规格: SMT贴片螺母M3 台阶高度1.53mm 台阶外径：4.09mm 螺柱长度：3.5MM; 规格编号: SMTSO3035CTJ; 条码: EBF29410007; 品牌: 雄和远景; 类别: 贴片螺母; 规格书: Sinhoo电路板表贴螺母柱_PCB_SMT_Nuts.pdf; 生命周期: 量产
footprint smtso-m3
pins: 1 NC_1

## SW_TH3P
designator SW?, comment TS-1091B-A5B3-D2  (value not drawn)
CLASS: IC; 价格: 0.249174; PCB Footprint: sw_th_3p_4r5x5r5; 生命周期: 量产; 规格书: 轻触开关4.5_4.5_5.5边三脚侧插侧按按键254GF.pdf; 类别: 直插按键; 品牌: 台湾元迪; 条码: EBF29310018; 规格: 轻触开关4.5_4.5_5.5边三脚侧插侧按按键254GF
footprint sw_th_3p_4r5x5r5
pins: 1 A1, 2 B1, 3 GND1

## TEST
designator J?, comment TP
PCB Footprint: tp_1mm; 生命周期: 量产; 类别: 测试点; 条码: EBF420008; 规格: 直径1mm
footprint tp_1mm
pins: 1

## TF_Card
designator J?
CLASS: IO; 可替代料: EBF29040003; 生命周期: 量产; 价格: 0.48; 规格书: 硕方-TF-015.pdf; 类别: SD卡连接器; 品牌: 硕方; 规格编号: TF-015; 规格: MICRO SD 卡座 TF T-Flash 外焊 双压片 自弹贴片; PCB Footprint: TFCARD
footprint TFCARD
pins: 1 DAT2, 2 CD/DAT3, 3 CMD, 4 VDD (power), 5 CLK, 6 VSS (power), 7 DAT0, 8 DAT1, 9 CD, 10 GND10, 11 GND11, 12 GND12, 13 GND13

## TitleBlock_YHSCH
designator *?  Doc: 目录  RevCode: V1.0  Title: 野火_EBF RK3568 底板  OrgName: 东莞野火电子技术有限公司  Page Number: 1  Page Count: 16  (hidden comment: TitleBlock_YHSCH)  (graphical)

## TJA1057GT3
designator U?, comment MAX3485
CLASS: IC; 生命周期: 量产; 价格: 1.31; 规格书: HTC_MAX3485ED.pdf; 类别: RS485/RS422芯片; 品牌: HTC; 条码: EBF29150034; 规格编号: MAX3485ED; 规格: RS-485/RS-422芯片 收发器 允许32个器件连接总线 协议类别RS-485 电源电压3.3V 数据速率10Mbps; PCB Footprint: SOP8
footprint SOP8
pins: 1 RXD, 2 ~{RE}, 3 DE, 4 TXD, 5 GND, 6 A, 7 B, 8 VCC

## TJA1057GT3_8P
designator U?, comment TJA1042T
CLASS: IC; 规格: CAN芯片 收发器 驱动器/接收器数：1/1 协议类别CAN总线 电源电压4.5V~5.5V 数据速率5Mbps; 规格编号: TJA1042T/3/1J; 条码: EBF29150007; 品牌: 恩智浦; 类别: CAN芯片; 规格书: TJA1042T_3_1J.pdf; 价格: 19.31; 生命周期: 量产; 丝印: A1042/3; PCB Footprint: SOP8
footprint SOP8
pins: 1 TXD (in), 2 GND (power), 3 VCC (power), 4 RXD (out), 5 VIO (power), 6 CANL (io), 7 CANH (io), 8 S (in)

## TP6327GS6
designator U?
PCB Footprint: SOT23_6; 规格: DC-DC电源芯片 可输出电流 3A 开关工作频率 600kHz 输出类型 Adjustable 输出电压的路数 1 最小输入电压 3.5V 最大输入电压 18V; 条码: EBF29110045; 品牌: 台舟; 类别: 电源管理-DCDC; 规格书: TP6327GS6.pdf; 价格: 0.962255; 生命周期: 量产
footprint SOT23_6
pins: 1 GND, 2 SW, 3 VIN, 4 FB, 5 EN, 6 BOOT

## TYPE-C-31-M-12
designator J?, comment TYPE-C
规格: Type-C母座 16P 贴片 USB-2.0 插座 高清传输接口 4固定插脚 双向; 规格编号: TYPE-C-31-M-12; 条码: EBF29040004; 品牌: 韩国韩容; 类别: USB接口; 规格书: TYPE-C-31-M-12母座贴片.pdf; 价格: 1.06; 生命周期: 量产
footprint TYPE-C-31-M-12
pins: A1 GND1, A4 VBUS1, A5 CC1, A6 DP1, A7 DN1, A8 SBU1, A9 VBUS2, A12 GND2, B1 GND4, B4 VBUS4, B5 CC2, B6 DP2, B7 DN2, B8 SBU2, B9 VBUS3, B12 GND3, C1 SH1, C2 SH2, C3 SH3, C4 SH4

## USB3D0_USB2D0-A-D
designator J?
规格: USB3.0_USB2.0母座; 规格编号: UEA1112C-UHS6-4F; 条码: EBF29040092; 类别: USB接口; 规格书: UEA1112C-UHS6-4F.pdf; 生命周期: 量产; PCB Footprint: USB3D0-AF-18P; 品牌: 富士康
footprint USB3D0-AF-18P
part A pins: 1 VBUS, 2 D-, 3 D+, 4 GND1, 5 RX-, 6 RX+, 7 GND2, 8 TX-, 9 TX+, 19 SH1, 20 SH2
part B pins: 10 VBUS, 11 D-, 12 D+, 13 GND1, 14 NC1, 15 NC2, 16 NC3, 17 NC4, 18 NC5, 21 SH1, 22 SH2

## USB-A-D
designator J?
生命周期: 量产; 价格: 0.22; 规格书: 精拓金-双层USB.pdf; 类别: USB接口; 品牌: 精拓金; 条码: EBF29020027; 规格编号: 907-111A1012D10200; 规格: 双层USB接口 A型接口 90度双排弯插脚 AF母座 焊接式
footprint USB-A-D
part A pins: 1 VBUS, 2 D-, 3 D+, 4 GND, 5 SH1, 6 SH2
part B pins: 7 VBUS, 8 D-, 9 D+, 10 GND, 11 SH1, 12 SH2

## W25QXX_8P
designator U?, comment W25Q32JWSSIQ/NC
PCB Footprint: SOIC8-208; 生命周期: 量产; 价格: 2.95; 规格书: 华邦W25Q32JWSSIQ.pdf; 类别: 存储器-Flash; 品牌: 华邦; 条码: EBF2950030; 规格: nor Flash 大小32Mb (4M x 8) 接口SPI-4I/O 工作电压1.7V~1.95V
footprint SOIC8-208
pins: 1 ~{CS}, 2 DO/IO1, 3 ~{WP}/IO2, 4 GND, 5 DI/IO0, 6 CLK, 7 HOLD/IO3, 8 VCC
